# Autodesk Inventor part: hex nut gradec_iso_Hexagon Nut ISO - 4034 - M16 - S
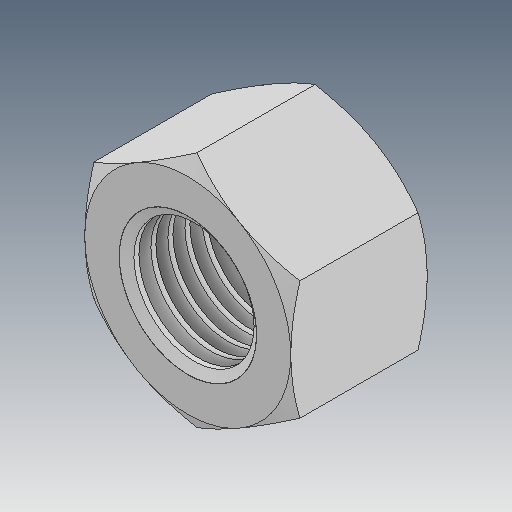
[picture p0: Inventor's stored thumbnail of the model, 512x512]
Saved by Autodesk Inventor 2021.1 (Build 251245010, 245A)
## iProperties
Created: 2019-04
Part Number: hex nut gradec_iso_Hexagon Nut ISO - 4034 - M16 - S
Material: Ogólny
Document SubType Name: Modeling
Designer: user
Density: 1 g/cm^3
Appearance: Domyślna
Author: user
Revision Number: ÈÎºÎ
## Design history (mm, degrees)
feature "ÊäÈë1"
node "Bryła1"
